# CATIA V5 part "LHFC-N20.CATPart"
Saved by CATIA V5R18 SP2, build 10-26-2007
Part number: LHFC-N20.catpart
Property "A": "36"
Property "AC": "Seal"
Property "ARTICLENO": "LHFC_N20"
Property "BOMINFO": "LHFC_N20"
Property "BR": "5"
Property "CATALOG": "Misumi"
Property "CD": "882"
Property "CH": "Standard"
Property "CO": "1370"
Property "CREATOR": "CADENAS GmbH"
Property "D": "32"
Property "DD": "5_5"
Property "DD1": "9_0"
Property "DDRR": "20"
Property "DDRRTOL": "0__0_010"
Property "DTOL": "0__0_019"
Property "ESS": "0_015"
Property "F": "24"
Property "GREASE": "N_A"
Property "H": "54"
Property "HARDOC": "58HRC_"
Property "L": "42"
Property "LINA": "LHFC_N20"
Property "LTOL": "_0_3"
Property "MASS": "167"
Property "MATB": "52100 Bearing Steel"
Property "MATOC": "52100 Bearing Steel"
Property "MATR": "Resin _Duracone M90 or Equivalent_"
Property "MATS": "Nitrile Rubber __20_120 deg Celsius_"
Property "NB": "LHFC_N20"
Property "NBSYN": "_PN_"
Property "NN": "LHZR_ LHFR_N_ LHFR_ LHFRF_ LHFRR_ LHFRM_ LHFRM_N_ LHFRMF_ SLHFR_ SLHFRS_ LHZS_ LHFS_N_ LHFS_ LHFSF_ LHFSR_ LHFSM_ LHFSM_N_ LHFSMF_ SLHFS_ SLHFSS_ LHZC_ LHFC_N_ LHFC_ LHFCF_ LHFCR_ LHFCM_ LHFCM_N_ LHFCMF_ SLHFC_ SLHFCS"
Property "NT": "Flanged Linear Bushings _ Single Standard Type_Opposite Counterbore Hole Type"
Property "OT": "_20_80"
Property "PCD": "0"
Property "PD": "0_015"
Property "PN": "LHFC_N20"
Property "STOC": "_"
Property "SUPPLIER": "MISUMI"
Property "T": "8_0"
Property "TS": "2 _ Flats Flange"
Property "TS1": "w_o Seal"
Property "TT": "5_1"
Property "W": "0"
Bounding box of the stored display mesh (mm): x 0 to 42, y -27 to 27, z -19 to 19
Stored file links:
  C:\Users\Administrator\Desktop\10-14 작업\stopper\LHFC-N20.CATPart
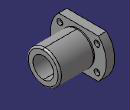
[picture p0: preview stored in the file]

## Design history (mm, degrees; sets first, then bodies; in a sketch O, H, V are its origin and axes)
Body1 "LHFC-N20.catpart" (main body)
  Solid1: solid without history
